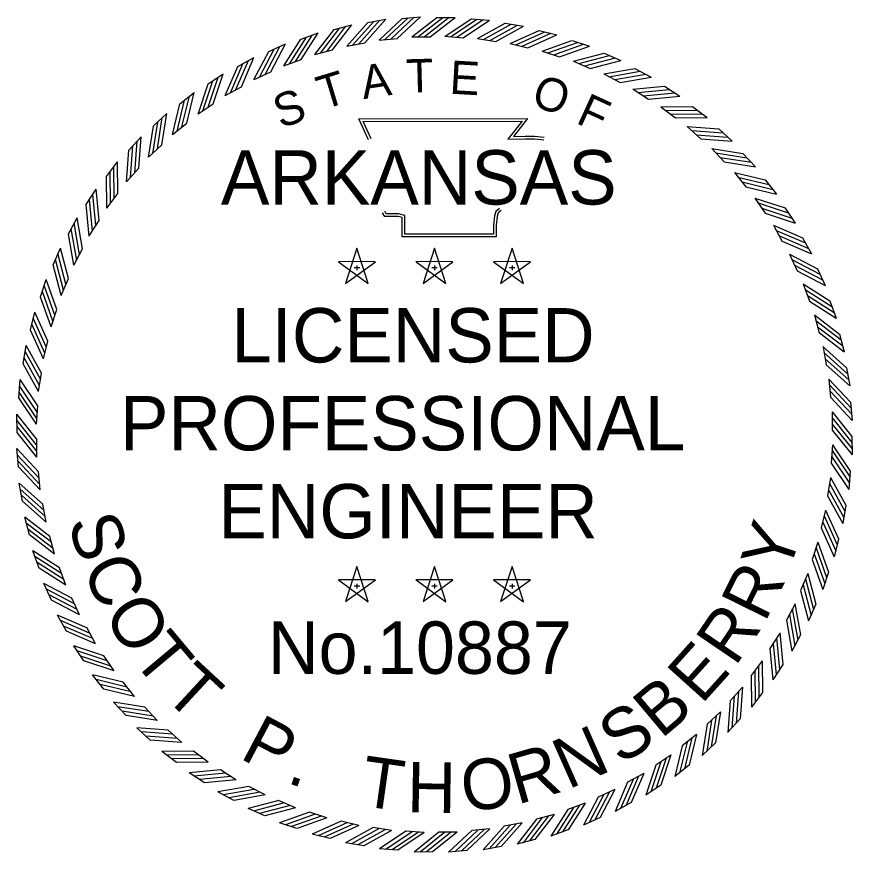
# Model space of a CAD drawing. Extents: x -4306 to 3843, y 131 to 8341.
# Drawn here: x 3046.5 to 3294.9, y 323.2 to 571.6 of the extents above; entities that cross this region are included whole.
import ezdxf

# ---------------------------------------------------------------- set-up
doc = ezdxf.new("R2010")
doc.units = 0
doc.layers.add('46', color=7, linetype='Continuous')

msp = doc.modelspace()

# ---------------------------------------------------------------- linework, layer by layer
at = {"layer": '46'}
for p, q in [((3161.08, 571.13), (3166.5, 571.63)), ((3171.39, 571.43), (3176.83, 571.43)), ((3140.85, 567.86), (3146.11, 569.24)), ((3150.9, 569.91), (3156.26, 570.86)), ((3181.58, 571.02), (3187, 570.63)), ((3191.75, 569.7), (3197.12, 568.86)), ((3131.01, 564.98), (3136.14, 566.8)), ((3201.77, 567.55), (3207.06, 566.26)), ((3154.22, 564.68), (3159.65, 565.18)), ((3163.96, 565.64), (3169.41, 565.64)), ((3173.75, 565.8), (3179.19, 565.4)), ((3183.51, 565.14), (3188.9, 564.29)), ((3211.59, 564.57), (3216.75, 562.85)), ((3121.43, 561.3), (3126.4, 563.53)), ((3135.14, 560.37), (3140.42, 561.76)), ((3144.59, 562.92), (3149.96, 563.87)), ((3193.19, 563.68), (3198.49, 562.39)), ((3112.2, 556.85), (3116.96, 559.48)), ((3202.71, 561.42), (3207.89, 559.7)), ((3221.12, 560.8), (3226.13, 558.66)), ((3125.94, 557.05), (3131.08, 558.87)), ((3212.02, 558.39), (3217.03, 556.25)), ((3103.36, 551.64), (3107.89, 554.66)), ((3117.04, 552.98), (3122.01, 555.21)), ((3221.04, 554.6), (3225.86, 552.05)), ((3230.31, 556.24), (3235.12, 553.7)), ((3094.98, 545.72), (3099.24, 549.11)), ((3108.5, 548.19), (3113.27, 550.83)), ((3229.72, 550.08), (3234.32, 547.14)), ((3239.1, 550.95), (3243.68, 548.02)), ((3100.39, 542.71), (3104.93, 545.73)), ((3238, 544.85), (3242.33, 541.54)), ((3247.41, 544.95), (3251.74, 541.64)), ((3087.12, 539.14), (3091.09, 542.86)), ((3092.76, 536.57), (3097.04, 539.96)), ((3245.82, 538.96), (3249.86, 535.3)), ((3255.21, 538.28), (3259.24, 534.63)), ((3079.83, 531.92), (3083.48, 535.96)), ((3085.67, 529.83), (3089.64, 533.56)), ((3253.12, 532.45), (3256.85, 528.47)), ((3262.42, 530.99), (3266.14, 527.02)), ((3073.17, 524.13), (3076.47, 528.45)), ((3079.15, 522.53), (3082.81, 526.58)), ((3259.86, 525.35), (3263.25, 521.08)), ((3269.01, 523.13), (3272.39, 518.87)), ((3067.16, 515.81), (3070.1, 520.39)), ((3073.26, 514.71), (3076.57, 519.05)), ((3265.99, 517.72), (3269.02, 513.18)), ((3274.93, 514.75), (3277.94, 510.23)), ((3061.87, 507.03), (3064.41, 511.84)), ((3068.04, 506.44), (3070.98, 511.03)), ((3271.47, 509.61), (3274.11, 504.84)), ((3280.13, 505.92), (3282.76, 501.15)), ((3057.32, 497.84), (3059.46, 502.84)), ((3063.51, 497.76), (3066.06, 502.58)), ((3147.61, 502.79), (3144.21, 492.34)), ((3151, 492.35), (3147.62, 502.8)), ((3170.69, 502.79), (3167.28, 492.34)), ((3174.08, 492.35), (3170.7, 502.8)), ((3193.77, 502.79), (3190.36, 492.34)), ((3197.16, 492.35), (3193.77, 502.8)), ((3276.26, 501.08), (3278.5, 496.1)), ((3153.1, 498.8), (3142.11, 498.81)), ((3142.12, 498.8), (3151, 492.33)), ((3144.22, 492.35), (3153.11, 498.8)), ((3146.83, 497.04), (3148.46, 497.04)), ((3147.62, 497.63), (3147.62, 496.25)), ((3176.18, 498.8), (3165.19, 498.81)), ((3165.2, 498.8), (3174.08, 492.33)), ((3167.3, 492.35), (3176.19, 498.8)), ((3169.91, 497.04), (3171.54, 497.04)), ((3170.7, 497.63), (3170.7, 496.25)), ((3199.25, 498.8), (3188.27, 498.81)), ((3188.28, 498.8), (3197.16, 492.33)), ((3190.37, 492.35), (3199.27, 498.8)), ((3192.98, 497.04), (3194.62, 497.04)), ((3193.78, 497.63), (3193.78, 496.25)), ((3284.59, 496.68), (3286.82, 491.72)), ((3053.54, 488.3), (3055.26, 493.47)), ((3059.72, 488.74), (3061.86, 493.75)), ((3280.33, 492.18), (3282.15, 487.03)), ((3288.27, 487.11), (3290.08, 481.98)), ((3056.69, 479.43), (3058.41, 484.6)), ((3050.56, 478.49), (3051.85, 483.78)), ((3283.66, 482.97), (3285.04, 477.69)), ((3291.14, 477.26), (3292.53, 472)), ((3054.43, 469.91), (3055.72, 475.2)), ((3048.41, 468.46), (3049.25, 473.84)), ((3286.21, 473.52), (3287.15, 468.15)), ((3293.2, 467.21), (3294.14, 461.86)), ((3052.97, 460.23), (3053.82, 465.61)), ((3047.09, 458.29), (3047.49, 463.72)), ((3287.97, 463.89), (3288.47, 458.46)), ((3052.32, 450.46), (3052.72, 455.9)), ((3294.41, 457.03), (3294.91, 451.61)), ((3046.61, 448.05), (3046.56, 453.49)), ((3288.93, 454.15), (3288.98, 448.7)), ((3052.47, 440.68), (3052.42, 446.13)), ((3294.79, 446.78), (3294.84, 441.34)), ((3046.98, 437.8), (3046.48, 443.22)), ((3289.08, 444.37), (3288.68, 438.93)), ((3053.43, 430.94), (3052.93, 436.37)), ((3294.31, 436.54), (3293.91, 431.11)), ((3048.2, 427.61), (3047.25, 432.97)), ((3288.42, 434.6), (3287.58, 429.21)), ((3055.19, 421.31), (3054.24, 426.68)), ((3286.96, 424.92), (3285.67, 419.62)), ((3292.99, 426.36), (3292.14, 420.99)), ((3050.25, 417.57), (3048.87, 422.83)), ((3057.74, 411.86), (3056.35, 417.13)), ((3284.71, 415.4), (3282.99, 410.22)), ((3290.83, 416.34), (3289.55, 411.05)), ((3053.13, 407.72), (3051.32, 412.85)), ((3061.06, 402.65), (3059.24, 407.79)), ((3147.61, 408.16), (3144.21, 397.72)), ((3151, 397.72), (3147.62, 408.17)), ((3170.69, 408.16), (3167.28, 397.72)), ((3174.08, 397.72), (3170.7, 408.17)), ((3193.77, 408.16), (3190.36, 397.72)), ((3197.16, 397.72), (3193.77, 408.17)), ((3281.68, 406.09), (3279.53, 401.08)), ((3287.86, 406.52), (3286.14, 401.36)), ((3056.81, 398.15), (3054.58, 403.11)), ((3153.1, 404.17), (3142.11, 404.19)), ((3142.12, 404.17), (3151, 397.71)), ((3144.22, 397.72), (3153.11, 404.17)), ((3147.62, 403.01), (3147.62, 401.63)), ((3176.18, 404.17), (3165.19, 404.19)), ((3165.2, 404.17), (3174.08, 397.71)), ((3167.3, 397.72), (3176.19, 404.17)), ((3170.7, 403.01), (3170.7, 401.63)), ((3199.25, 404.17), (3188.27, 404.19)), ((3188.28, 404.17), (3197.16, 397.71)), ((3190.37, 397.72), (3199.27, 404.17)), ((3193.78, 403.01), (3193.78, 401.63)), ((3146.83, 402.42), (3148.46, 402.42)), ((3169.91, 402.42), (3171.54, 402.42)), ((3192.98, 402.42), (3194.62, 402.42)), ((3065.13, 393.75), (3062.9, 398.72)), ((3277.89, 397.07), (3275.33, 392.25)), ((3284.08, 396.99), (3281.94, 391.99)), ((3061.27, 388.91), (3058.63, 393.67)), ((3069.93, 385.22), (3067.29, 389.99)), ((3273.36, 388.39), (3270.42, 383.8)), ((3279.53, 387.8), (3276.98, 382.99)), ((3066.47, 380.07), (3063.45, 384.6)), ((3075.41, 377.11), (3072.38, 381.65)), ((3268.14, 380.11), (3264.83, 375.78)), ((3274.23, 379.01), (3271.3, 374.43)), ((3072.39, 371.7), (3069.01, 375.96)), ((3081.54, 369.48), (3078.15, 373.75)), ((3262.25, 372.3), (3258.59, 368.25)), ((3268.23, 370.7), (3264.93, 366.37)), ((3078.98, 363.84), (3075.25, 367.81)), ((3088.28, 362.38), (3084.55, 366.36)), ((3255.73, 364.99), (3251.75, 361.26)), ((3261.56, 362.91), (3257.92, 358.87)), ((3086.19, 356.55), (3082.15, 360.2)), ((3095.58, 355.87), (3091.54, 359.52)), ((3248.63, 358.25), (3244.36, 354.86)), ((3254.27, 355.69), (3250.31, 351.97)), ((3093.98, 349.88), (3089.66, 353.18)), ((3103.4, 349.98), (3099.06, 353.29)), ((3241, 352.12), (3236.47, 349.1)), ((3246.41, 349.1), (3242.15, 345.72)), ((3102.3, 343.88), (3097.72, 346.81)), ((3111.67, 344.75), (3107.08, 347.69)), ((3232.9, 346.64), (3228.12, 344)), ((3238.04, 343.19), (3233.51, 340.17)), ((3111.08, 338.58), (3106.27, 341.13)), ((3120.35, 340.23), (3115.53, 342.78)), ((3224.36, 341.85), (3219.39, 339.61)), ((3129.38, 336.44), (3124.36, 338.58)), ((3229.2, 337.98), (3224.44, 335.35)), ((3120.27, 334.03), (3115.27, 336.17)), ((3215.46, 337.78), (3210.32, 335.96)), ((3138.68, 333.4), (3133.51, 335.13)), ((3206.25, 334.46), (3200.98, 333.07)), ((3219.96, 333.52), (3215, 331.29)), ((3129.81, 330.26), (3124.65, 331.97)), ((3148.21, 331.15), (3142.91, 332.44)), ((3157.88, 329.69), (3152.5, 330.54)), ((3196.8, 331.91), (3191.43, 330.96)), ((3139.62, 327.28), (3134.34, 328.57)), ((3167.65, 329.03), (3162.21, 329.43)), ((3177.44, 329.18), (3171.98, 329.13)), ((3187.18, 330.14), (3181.75, 329.64)), ((3210.39, 329.84), (3205.26, 328.03)), ((3149.65, 325.12), (3144.28, 325.97)), ((3200.55, 326.97), (3195.28, 325.58)), ((3159.82, 323.8), (3154.39, 324.2)), ((3170.07, 323.33), (3164.62, 323.28)), ((3180.31, 323.7), (3174.9, 323.2)), ((3190.5, 324.91), (3185.14, 323.97))]:
    msp.add_line(p, q, dxfattribs=at)
for points in [[(3157.84, 565.04), (3164.7, 571.48)], [(3159.64, 565.19), (3166.5, 571.63)], [(3163.95, 565.64), (3171.38, 571.43)], [(3165.71, 565.62), (3173.13, 571.41)], [(3167.6, 565.66), (3175.02, 571.45)], [(3169.41, 565.65), (3176.83, 571.44)], [(3140.41, 561.76), (3146.12, 569.25)], [(3144.59, 562.92), (3150.89, 569.91)], [(3146.31, 563.2), (3152.62, 570.19)], [(3148.17, 563.57), (3154.47, 570.56)], [(3149.96, 563.87), (3156.26, 570.86)], [(3154.21, 564.68), (3161.08, 571.12)], [(3155.96, 564.82), (3162.82, 571.27)], [(3173.74, 565.79), (3181.57, 571.02)], [(3175.49, 565.65), (3183.31, 570.88)], [(3177.37, 565.55), (3185.2, 570.78)], [(3179.18, 565.4), (3187.01, 570.63)], [(3183.51, 565.14), (3191.74, 569.7)], [(3185.23, 564.85), (3193.47, 569.41)], [(3187.11, 564.59), (3195.34, 569.16)], [(3131.07, 558.87), (3136.14, 566.8)], [(3135.14, 560.36), (3140.84, 567.85)], [(3136.84, 560.79), (3142.54, 568.28)], [(3138.65, 561.32), (3144.36, 568.8)], [(3188.89, 564.3), (3197.13, 568.86)], [(3193.18, 563.68), (3201.77, 567.55)], [(3194.88, 563.25), (3203.46, 567.12)], [(3196.73, 562.84), (3205.31, 566.71)], [(3125.93, 557.04), (3131, 564.98)], [(3127.59, 557.61), (3132.66, 565.54)], [(3129.36, 558.28), (3134.42, 566.21)], [(3198.48, 562.39), (3207.07, 566.26)], [(3202.71, 561.42), (3211.58, 564.57)], [(3204.36, 560.85), (3213.24, 564)], [(3118.64, 553.67), (3123.03, 562)], [(3120.34, 554.49), (3124.74, 562.81)], [(3122, 555.22), (3126.4, 563.54)], [(3206.17, 560.3), (3215.04, 563.44)], [(3207.88, 559.71), (3216.76, 562.85)], [(3113.27, 550.83), (3116.96, 559.49)], [(3117.03, 552.97), (3121.43, 561.3)], [(3212.01, 558.39), (3221.11, 560.79)], [(3213.62, 557.69), (3222.72, 560.09)], [(3215.37, 556.98), (3224.47, 559.39)], [(3108.5, 548.18), (3112.19, 556.84)], [(3110.04, 549.01), (3113.73, 557.67)], [(3111.67, 549.96), (3115.37, 558.62)], [(3217.03, 556.25), (3226.13, 558.66)], [(3104.92, 545.73), (3107.89, 554.67)], [(3221.04, 554.6), (3230.31, 556.24)], [(3222.58, 553.77), (3231.85, 555.41)], [(3224.27, 552.92), (3233.54, 554.56)], [(3100.39, 542.7), (3103.36, 551.63)], [(3101.86, 543.66), (3104.82, 552.59)], [(3103.41, 544.74), (3106.37, 553.67)], [(3225.86, 552.06), (3235.13, 553.7)], [(3097.03, 539.96), (3099.25, 549.11)], [(3229.71, 550.08), (3239.09, 550.95)], [(3231.18, 549.12), (3240.55, 549.99)], [(3094.14, 537.64), (3096.36, 546.79)], [(3095.6, 538.85), (3097.82, 548)], [(3232.8, 548.13), (3242.17, 549.01)], [(3234.31, 547.14), (3243.69, 548.02)], [(3092.76, 536.57), (3094.98, 545.72)], [(3237.99, 544.85), (3247.4, 544.95)], [(3088.3, 532.34), (3089.76, 541.64)], [(3089.64, 533.56), (3091.09, 542.86)], [(3239.37, 543.78), (3248.79, 543.87)], [(3240.9, 542.66), (3250.31, 542.76)], [(3242.33, 541.55), (3251.74, 541.64)], [(3085.67, 529.83), (3087.12, 539.13)], [(3086.95, 531.01), (3088.41, 540.31)], [(3151.11, 535.02), (3148.21, 541.3), (3198.39, 541.33), (3194.2, 536.06), (3197.61, 536.11), (3200.46, 536.14), (3203.3, 535.83)], [(3151.84, 535.35), (3149.46, 540.5), (3196.74, 540.53), (3192.54, 535.24), (3197.62, 535.31), (3200.42, 535.35), (3203.22, 535.04)], [(3245.81, 538.96), (3255.2, 538.28)], [(3247.1, 537.78), (3256.49, 537.09)], [(3081.57, 525.24), (3082.25, 534.63)], [(3082.8, 526.57), (3083.48, 535.96)], [(3248.53, 536.54), (3257.92, 535.86)], [(3249.86, 535.31), (3259.25, 534.63)], [(3079.15, 522.52), (3079.83, 531.91)], [(3080.34, 523.81), (3081.02, 533.2)], [(3253.11, 532.45), (3262.41, 530.99)], [(3254.3, 531.16), (3263.6, 529.7)], [(3255.62, 529.81), (3264.92, 528.35)], [(3075.45, 517.62), (3075.35, 527.03)], [(3076.56, 519.05), (3076.47, 528.46)], [(3256.85, 528.47), (3266.15, 527.02)], [(3074.34, 516.09), (3074.24, 525.5)], [(3259.85, 525.35), (3269, 523.13)], [(3073.26, 514.71), (3073.16, 524.12)], [(3260.93, 523.97), (3270.08, 521.75)], [(3262.13, 522.51), (3271.28, 520.3)], [(3070.97, 511.03), (3070.1, 520.4)], [(3263.25, 521.08), (3272.4, 518.87)], [(3068.99, 507.9), (3068.12, 517.27)], [(3069.98, 509.51), (3069.1, 518.88)], [(3265.98, 517.72), (3274.92, 514.76)], [(3068.04, 506.43), (3067.16, 515.8)], [(3189.98, 514.61), (3188.93, 513.75), (3188.56, 512.4), (3188.27, 509.7), (3188.27, 506.98), (3161.85, 506.98), (3161.85, 510.87), (3161.85, 512.49), (3160.03, 513.05), (3156.36, 513.05), (3155.89, 513.77)], [(3266.94, 516.26), (3275.88, 513.29)], [(3268.02, 514.71), (3276.96, 511.74)], [(3066.06, 502.57), (3064.41, 511.84)], [(3190.49, 513.99), (3189.63, 513.29), (3189.35, 512.25), (3189.06, 509.65), (3189.06, 506.18), (3161.05, 506.18), (3161.05, 510.87), (3161.05, 511.91), (3159.91, 512.25), (3155.93, 512.25), (3155.22, 513.33)], [(3269.02, 513.19), (3277.95, 510.22)], [(3065.19, 500.98), (3063.55, 510.25)], [(3271.46, 509.61), (3280.12, 505.92)], [(3063.51, 497.75), (3061.87, 507.02)], [(3064.35, 499.29), (3062.7, 508.56)], [(3272.3, 508.07), (3280.96, 504.38)], [(3273.25, 506.44), (3281.91, 502.75)], [(3274.11, 504.85), (3282.77, 501.15)], [(3061.86, 493.75), (3059.46, 502.85)], [(3060.43, 490.33), (3058.02, 499.43)], [(3061.13, 492.09), (3058.73, 501.19)], [(3276.26, 501.08), (3284.58, 496.68)], [(3276.96, 499.48), (3285.28, 495.08)], [(3059.72, 488.73), (3057.32, 497.83)], [(3277.77, 497.77), (3286.1, 493.37)], [(3278.5, 496.11), (3286.83, 491.71)], [(3058.4, 484.6), (3055.26, 493.47)], [(3280.33, 492.18), (3288.26, 487.11)], [(3057.26, 481.08), (3054.11, 489.95)], [(3057.82, 482.88), (3054.67, 491.76)], [(3280.9, 490.52), (3288.83, 485.46)], [(3056.69, 479.42), (3053.54, 488.29)], [(3281.57, 488.76), (3289.5, 483.69)], [(3282.15, 487.04), (3290.09, 481.97)], [(3055.27, 473.44), (3051.4, 482.02)], [(3055.72, 475.2), (3051.85, 483.78)], [(3283.65, 482.97), (3291.14, 477.27)], [(3054.87, 471.6), (3051, 480.18)], [(3284.08, 481.28), (3291.57, 475.57)], [(3054.44, 469.9), (3050.57, 478.48)], [(3284.6, 479.46), (3292.09, 473.75)], [(3285.05, 477.7), (3292.53, 472)], [(3053.52, 463.82), (3048.95, 472.05)], [(3053.82, 465.61), (3049.25, 473.84)], [(3286.2, 473.53), (3293.19, 467.22)], [(3053.26, 461.95), (3048.7, 470.18)], [(3286.49, 471.8), (3293.48, 465.49)], [(3286.86, 469.94), (3293.85, 463.64)], [(3052.98, 460.22), (3048.41, 468.45)], [(3287.16, 468.16), (3294.15, 461.85)], [(3052.71, 455.89), (3047.48, 463.72)], [(3287.96, 463.9), (3294.41, 457.04)], [(3288.11, 462.15), (3294.55, 455.29)], [(3052.47, 452.2), (3047.24, 460.03)], [(3052.56, 454.09), (3047.33, 461.92)], [(3288.32, 460.27), (3294.77, 453.41)], [(3052.32, 450.46), (3047.09, 458.28)], [(3288.47, 458.47), (3294.92, 451.61)], [(3052.41, 446.12), (3046.56, 453.49)], [(3288.92, 454.16), (3294.78, 446.79)], [(3288.92, 452.41), (3294.78, 445.04)], [(3052.41, 444.31), (3046.56, 451.68)], [(3052.47, 442.42), (3046.62, 449.79)], [(3288.98, 450.52), (3294.84, 443.15)], [(3052.47, 440.67), (3046.62, 448.04)], [(3288.98, 448.7), (3294.84, 441.33)], [(3052.93, 436.36), (3046.48, 443.22)], [(3288.93, 442.63), (3294.16, 434.8)], [(3289.08, 444.37), (3294.31, 436.54)], [(3053.08, 434.55), (3046.63, 441.41)], [(3288.83, 440.74), (3294.06, 432.91)], [(3053.29, 432.67), (3046.84, 439.54)], [(3053.43, 430.93), (3046.99, 437.79)], [(3288.68, 438.93), (3293.91, 431.1)], [(3054.24, 426.67), (3047.25, 432.98)], [(3288.13, 432.88), (3292.7, 424.65)], [(3288.42, 434.61), (3292.99, 426.37)], [(3054.54, 424.88), (3047.55, 431.19)], [(3287.88, 431.01), (3292.44, 422.77)], [(3054.91, 423.03), (3047.92, 429.33)], [(3055.2, 421.3), (3048.21, 427.61)], [(3287.58, 429.22), (3292.15, 420.98)], [(3286.96, 424.93), (3290.83, 416.35)], [(3056.35, 417.13), (3048.86, 422.83)], [(3286.53, 423.23), (3290.4, 414.65)], [(3056.8, 415.37), (3049.31, 421.07)], [(3286.12, 421.39), (3289.99, 412.8)], [(3057.32, 413.55), (3049.83, 419.26)], [(3057.75, 411.85), (3050.26, 417.56)], [(3285.68, 419.63), (3289.55, 411.05)], [(3284.71, 415.41), (3287.85, 406.53)], [(3059.24, 407.79), (3051.31, 412.85)], [(3284.14, 413.75), (3287.29, 404.88)], [(3059.83, 406.07), (3051.9, 411.14)], [(3282.99, 410.23), (3286.14, 401.36)], [(3283.58, 411.94), (3286.73, 403.07)], [(3060.5, 404.3), (3052.57, 409.37)], [(3061.07, 402.65), (3053.14, 407.72)], [(3281.67, 406.1), (3284.08, 397)], [(3062.9, 398.72), (3054.57, 403.11)], [(3280.27, 402.74), (3282.67, 393.64)], [(3280.97, 404.5), (3283.37, 395.39)], [(3063.62, 397.06), (3055.3, 401.45)], [(3279.54, 401.08), (3281.94, 391.98)], [(3064.44, 395.35), (3056.11, 399.75)], [(3065.14, 393.75), (3056.82, 398.14)], [(3277.05, 395.54), (3278.69, 386.27)], [(3277.88, 397.08), (3279.53, 387.81)], [(3067.29, 389.98), (3058.63, 393.67)], [(3276.2, 393.85), (3277.85, 384.58)], [(3068.15, 388.39), (3059.49, 392.08)], [(3069.1, 386.75), (3060.44, 390.45)], [(3275.34, 392.25), (3276.98, 382.98)], [(3069.93, 385.21), (3061.27, 388.91)], [(3273.36, 388.4), (3274.23, 379.02)], [(3271.42, 385.32), (3272.29, 375.94)], [(3272.4, 386.93), (3273.28, 377.56)], [(3072.38, 381.64), (3063.45, 384.6)], [(3073.37, 380.12), (3064.44, 383.09)], [(3270.43, 383.8), (3271.3, 374.43)], [(3074.46, 378.57), (3065.52, 381.54)], [(3268.14, 380.12), (3268.23, 370.71)], [(3075.41, 377.1), (3066.48, 380.07)], [(3267.06, 378.74), (3267.16, 369.33)], [(3078.15, 373.74), (3069, 375.96)], [(3264.83, 375.78), (3264.93, 366.37)], [(3265.95, 377.21), (3266.04, 367.8)], [(3079.26, 372.31), (3070.11, 374.53)], [(3080.47, 370.86), (3071.32, 373.08)], [(3081.55, 369.48), (3072.4, 371.69)], [(3261.06, 371.02), (3260.38, 361.63)], [(3262.25, 372.3), (3261.57, 362.91)], [(3084.55, 366.35), (3075.25, 367.81)], [(3258.6, 368.25), (3257.92, 358.86)], [(3259.82, 369.59), (3259.14, 360.2)], [(3085.78, 365.02), (3076.48, 366.47)], [(3087.1, 363.67), (3077.8, 365.12)], [(3088.29, 362.38), (3078.98, 363.84)], [(3254.44, 363.81), (3252.99, 354.51)], [(3255.73, 365), (3254.28, 355.7)], [(3251.76, 361.26), (3250.3, 351.96)], [(3253.09, 362.49), (3251.64, 353.19)], [(3091.54, 359.52), (3082.15, 360.2)], [(3092.87, 358.29), (3083.48, 358.97)], [(3248.64, 358.26), (3246.42, 349.11)], [(3094.3, 357.05), (3084.91, 357.73)], [(3095.59, 355.87), (3086.2, 356.55)], [(3245.8, 355.98), (3243.58, 346.83)], [(3247.25, 357.18), (3245.04, 348.04)], [(3099.07, 353.28), (3089.65, 353.18)], [(3244.37, 354.86), (3242.15, 345.72)], [(3100.5, 352.16), (3091.08, 352.07)], [(3102.02, 351.05), (3092.61, 350.96)], [(3239.54, 351.17), (3236.58, 342.24)], [(3241.01, 352.13), (3238.04, 343.19)], [(3103.41, 349.98), (3093.99, 349.88)], [(3236.47, 349.1), (3233.51, 340.16)], [(3237.99, 350.09), (3235.03, 341.15)], [(3107.08, 347.68), (3097.71, 346.81)], [(3108.6, 346.69), (3099.23, 345.82)], [(3110.22, 345.71), (3100.84, 344.84)], [(3231.36, 345.81), (3227.66, 337.16)], [(3232.9, 346.65), (3229.2, 337.99)], [(3111.68, 344.75), (3102.31, 343.88)], [(3228.13, 344), (3224.44, 335.34)], [(3229.72, 344.86), (3226.03, 336.2)], [(3115.54, 342.77), (3106.27, 341.13)], [(3117.13, 341.91), (3107.86, 340.27)], [(3118.82, 341.06), (3109.55, 339.42)], [(3222.76, 341.15), (3218.37, 332.83)], [(3224.36, 341.86), (3219.97, 333.53)], [(3120.36, 340.23), (3111.09, 338.58)], [(3124.37, 338.57), (3115.26, 336.17)], [(3219.39, 339.61), (3215, 331.29)], [(3221.05, 340.34), (3216.66, 332.01)], [(3126.03, 337.85), (3116.92, 335.44)], [(3127.78, 337.14), (3118.68, 334.74)], [(3129.38, 336.44), (3120.28, 334.03)], [(3210.33, 335.96), (3205.26, 328.02)], [(3212.04, 336.55), (3206.97, 328.61)], [(3213.81, 337.22), (3208.74, 329.28)], [(3215.46, 337.78), (3210.4, 329.85)], [(3133.51, 335.12), (3124.64, 331.97)], [(3135.23, 334.53), (3126.35, 331.38)], [(3137.03, 333.97), (3128.16, 330.83)], [(3138.69, 333.41), (3129.82, 330.26)], [(3200.99, 333.07), (3195.28, 325.58)], [(3202.74, 333.51), (3197.04, 326.02)], [(3204.56, 334.03), (3198.85, 326.54)], [(3206.26, 334.46), (3200.55, 326.97)], [(3142.91, 332.43), (3134.33, 328.56)], [(3144.67, 331.99), (3136.09, 328.12)], [(3146.52, 331.58), (3137.93, 327.71)], [(3148.21, 331.15), (3139.63, 327.28)], [(3152.5, 330.53), (3144.27, 325.97)], [(3191.44, 330.96), (3185.14, 323.96)], [(3193.23, 331.25), (3186.92, 324.26)], [(3195.08, 331.62), (3188.78, 324.63)], [(3196.81, 331.91), (3190.5, 324.92)], [(3154.29, 330.23), (3146.06, 325.67)], [(3156.16, 329.98), (3147.93, 325.42)], [(3157.89, 329.69), (3149.66, 325.13)], [(3162.22, 329.43), (3154.39, 324.2)], [(3164.02, 329.28), (3156.2, 324.05)], [(3165.91, 329.18), (3158.08, 323.95)], [(3167.66, 329.04), (3159.83, 323.81)], [(3171.99, 329.13), (3164.62, 323.27)], [(3173.8, 329.13), (3166.43, 323.27)], [(3175.69, 329.19), (3168.32, 323.33)], [(3177.44, 329.19), (3170.07, 323.33)], [(3181.75, 329.64), (3174.89, 323.19)], [(3183.56, 329.79), (3176.7, 323.34)], [(3185.44, 330.01), (3178.58, 323.56)], [(3187.18, 330.15), (3180.32, 323.7)]]:
    msp.add_lwpolyline(points, dxfattribs=at)

# ---------------------------------------------------------------- texts
for s, height, rotation, p in [('T', 9.9, 1.4789, (3162.37, 549.07)), ('A', 9.9, 8.6788, (3149.58, 547.1)), ('E', 9.9, 356.672, (3175.03, 548.77)), ('T', 9.9, 16.9015, (3137.57, 543.96)), ('O', 9.9, 341.2218, (3199.07, 545.37)), ('S', 9.9, 19.7726, (3124.98, 538.31)), ('F', 9.9, 335.3628, (3212.41, 540.16)), ('S', 15.03, 286.9475, (3061.59, 421.47)), ('Y', 15.03, 71.7733, (3275.78, 405.43)), ('C', 15.03, 294.2435, (3065.77, 407.76)), ('R', 15.03, 63.7477, (3268.9, 391.25)), ('O', 15.03, 301.9044, (3071.99, 394.05)), ('R', 15.03, 55.7221, (3260.1, 378.16)), ('T', 15.03, 309.93, (3080.41, 380.72)), ('E', 15.03, 48.0613, (3250.08, 366.93)), ('T', 15.03, 317.226, (3089.62, 369.73)), ('B', 15.03, 40.0357, (3238.07, 356.71)), ('S', 15.03, 32.7397, (3226.01, 348.95)), ('P', 15.03, 332.1828, (3112.43, 351.3)), ('N', 15.03, 23.9845, (3210.39, 341.76)), ('R', 15.03, 15.9589, (3195.26, 337.33)), ('T', 15.03, 351.882, (3148.26, 337.1)), ('O', 15.03, 7.9332, (3179.65, 335.05)), ('H', 15.03, 359.178, (3162.46, 335.08)), ('.', 15.03, 340.2084, (3126.42, 344.03))]:
    msp.add_text(s, height=height, rotation=rotation, dxfattribs=at).set_placement(p)
for s, height, p in [('ARKANSAS', 16.155, (3107.2, 515.79)), ('LICENSED', 16.155, (3110.27, 468.84)), ('PROFESSIONAL', 16.1547, (3077.19, 442.69)), ('ENGINEER', 16.155, (3106.43, 416.53)), ('No.10887', 15.578, (3121.19, 376.25))]:
    msp.add_text(s, height=height, dxfattribs=at).set_placement(p)

doc.saveas('drawing.dxf')
